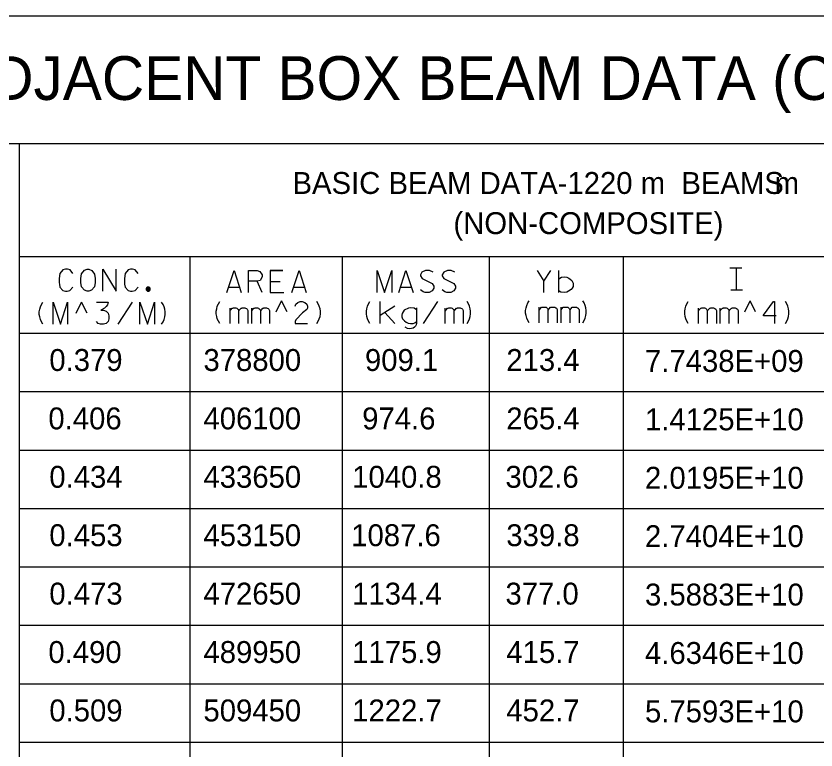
# Model space of a CAD drawing. Extents: x 635698 to 639877, y 296617 to 300175.
# Drawn here: x 635904.4 to 636014, y 299938.2 to 300038.7 of the extents above; entities that cross this region are included whole.
import ezdxf

# ---------------------------------------------------------------- set-up
doc = ezdxf.new("R2010")
doc.units = 0
doc.layers.add('2', color=7, linetype='Continuous')

msp = doc.modelspace()

# ---------------------------------------------------------------- linework, layer by layer
at = {"layer": '2'}
for p, q in [((636461.71, 300038.71), (635698.21, 300038.71)), ((636454.58, 300021.21), (635703.83, 300021.21)), ((635904.83, 300021.21), (635904.83, 299883.21)), ((636087.71, 300005.71), (635904.83, 300005.71)), ((635928.21, 300005.71), (635928.21, 299883.21)), ((635949.08, 300005.71), (635949.08, 299883.21)), ((635969.21, 300005.71), (635969.21, 299883.21)), ((635987.58, 300005.71), (635987.58, 299883.21)), ((636002.21, 300004.21), (636003.83, 300004.21)), ((636002.33, 300001.21), (636003.96, 300001.21)), ((635912.63, 299998.02), (635913.38, 299999.52)), ((635914.13, 299998.02), (635913.38, 299999.52)), ((635940.04, 299998.2), (635940.79, 299999.7)), ((635941.54, 299998.2), (635940.79, 299999.7)), ((636004.24, 299998.2), (636004.99, 299999.7)), ((636005.74, 299998.2), (636004.99, 299999.7)), ((636087.71, 299995.21), (635904.83, 299995.21)), ((636087.71, 299987.21), (635904.83, 299987.21)), ((636087.71, 299979.21), (635904.83, 299979.21)), ((636087.71, 299971.21), (635904.83, 299971.21)), ((636087.71, 299963.21), (635904.83, 299963.21)), ((636087.71, 299955.21), (635904.83, 299955.21)), ((636087.71, 299947.21), (635904.83, 299947.21)), ((636087.71, 299939.21), (635904.83, 299939.21))]:
    msp.add_line(p, q, dxfattribs=at)
for points in [[(635912.19, 300003.43), (635911.81, 300003.93), (635911.43, 300004.02), (635911.17, 300004.02), (635910.82, 300003.93), (635910.42, 300003.43), (635910.32, 300002.77), (635910.32, 300002.41), (635910.32, 300002.18), (635910.35, 300001.97), (635910.42, 300001.59), (635910.82, 300001.12), (635911.17, 300001.02), (635911.39, 300001.02), (635911.79, 300001.12), (635912.19, 300001.59)], [(635914.15, 300004.02), (635914.39, 300004.02), (635914.79, 300003.86), (635915.17, 300003.36), (635915.26, 300002.77), (635915.26, 300002.23), (635915.17, 300001.63), (635914.76, 300001.14), (635914.39, 300001.02), (635914.15, 300001.02), (635913.8, 300001.14), (635913.39, 300001.63), (635913.3, 300002.23), (635913.3, 300002.77), (635913.39, 300003.38), (635913.8, 300003.88), (635914.15, 300004.02)], [(635916.28, 300001.02), (635916.28, 300004.02), (635918.14, 300001.02), (635918.14, 300004.02)], [(635921.12, 300003.43), (635920.74, 300003.93), (635920.36, 300004.02), (635920.1, 300004.02), (635919.75, 300003.93), (635919.35, 300003.43), (635919.25, 300002.77), (635919.25, 300002.41), (635919.25, 300002.18), (635919.28, 300001.97), (635919.35, 300001.59), (635919.75, 300001.12), (635920.1, 300001.02), (635920.32, 300001.02), (635920.72, 300001.12), (635921.12, 300001.59)], [(635933.28, 300000.84), (635934.27, 300003.84), (635935.24, 300000.84)], [(635936.26, 300000.84), (635936.26, 300003.84), (635937.46, 300003.84), (635937.82, 300003.72), (635938.12, 300003.25), (635938.12, 300002.97), (635937.84, 300002.49), (635937.46, 300002.38), (635936.26, 300002.38)], [(635940.96, 300003.84), (635939.24, 300003.84), (635939.24, 300000.84), (635941.08, 300000.84)], [(635939.24, 300003.84), (635940.96, 300003.84)], [(635942.21, 300000.84), (635943.2, 300003.84), (635944.17, 300000.84)], [(635953.86, 300000.84), (635953.86, 300003.84), (635954.9, 300000.84), (635955.87, 300003.84), (635955.87, 300000.84)], [(635956.84, 300000.84), (635957.83, 300003.84), (635958.8, 300000.84)], [(635961.54, 300003.63), (635961.06, 300003.84), (635960.52, 300003.84), (635960.02, 300003.63), (635959.81, 300003.25), (635959.81, 300003.11), (635960.05, 300002.75), (635961.42, 300002.05), (635961.65, 300001.71), (635961.63, 300001.43), (635961.42, 300001.05), (635961.02, 300000.84), (635960.45, 300000.84), (635960.19, 300000.94), (635959.81, 300001.2)], [(635964.51, 300003.63), (635964.04, 300003.84), (635963.5, 300003.84), (635963, 300003.63), (635962.79, 300003.25), (635962.79, 300003.11), (635963.02, 300002.75), (635964.39, 300002.05), (635964.63, 300001.71), (635964.61, 300001.43), (635964.39, 300001.05), (635963.99, 300000.84), (635963.43, 300000.84), (635963.17, 300000.94), (635962.79, 300001.2)], [(635975.79, 300003.84), (635976.73, 300002.4), (635977.68, 300003.84)], [(635978.76, 300000.84), (635978.76, 300003.84)], [(636002.74, 300004.21), (636003.45, 300004.21)], [(636003.1, 300001.21), (636003.1, 300004.21)], [(635978.76, 300002.73), (635979.14, 300002.94), (635979.52, 300002.99), (635979.85, 300002.94), (635980.16, 300002.8), (635980.35, 300002.68), (635980.54, 300002.47), (635980.63, 300002.28), (635980.72, 300002.12), (635980.72, 300001.67), (635980.58, 300001.41), (635980.46, 300001.27), (635980.11, 300001.01), (635979.87, 300000.89), (635979.52, 300000.84), (635979.05, 300000.89), (635978.76, 300001.08)], [(635922.8, 300001.31), (635922.8, 300001.34), (635922.79, 300001.36), (635922.78, 300001.39), (635922.77, 300001.42), (635922.76, 300001.45), (635922.74, 300001.47), (635922.73, 300001.5), (635922.7, 300001.52), (635922.68, 300001.54), (635922.66, 300001.55), (635922.63, 300001.57), (635922.6, 300001.58), (635922.57, 300001.58), (635922.54, 300001.59), (635922.51, 300001.59), (635922.48, 300001.59), (635922.45, 300001.58), (635922.43, 300001.58), (635922.4, 300001.57), (635922.37, 300001.55), (635922.35, 300001.54), (635922.32, 300001.52), (635922.3, 300001.5), (635922.28, 300001.47), (635922.27, 300001.45), (635922.25, 300001.42), (635922.24, 300001.39), (635922.24, 300001.36), (635922.23, 300001.34), (635922.23, 300001.31), (635922.23, 300001.28), (635922.24, 300001.25), (635922.24, 300001.22), (635922.25, 300001.19), (635922.27, 300001.16), (635922.28, 300001.14), (635922.3, 300001.11), (635922.32, 300001.09), (635922.35, 300001.07), (635922.37, 300001.06), (635922.4, 300001.05), (635922.43, 300001.03), (635922.45, 300001.03), (635922.48, 300001.02), (635922.51, 300001.02), (635922.54, 300001.02), (635922.57, 300001.03), (635922.6, 300001.03), (635922.63, 300001.05), (635922.66, 300001.06), (635922.68, 300001.07), (635922.7, 300001.09), (635922.73, 300001.11), (635922.74, 300001.14), (635922.76, 300001.16), (635922.77, 300001.19), (635922.78, 300001.22), (635922.79, 300001.25), (635922.8, 300001.28), (635922.8, 300001.31)], [(635922.74, 300001.31), (635922.74, 300001.33), (635922.73, 300001.35), (635922.73, 300001.38), (635922.72, 300001.4), (635922.71, 300001.42), (635922.7, 300001.44), (635922.68, 300001.46), (635922.66, 300001.47), (635922.65, 300001.49), (635922.63, 300001.5), (635922.61, 300001.51), (635922.58, 300001.52), (635922.56, 300001.53), (635922.54, 300001.53), (635922.51, 300001.53), (635922.49, 300001.53), (635922.47, 300001.53), (635922.44, 300001.52), (635922.42, 300001.51), (635922.4, 300001.5), (635922.38, 300001.49), (635922.36, 300001.47), (635922.35, 300001.46), (635922.33, 300001.44), (635922.32, 300001.42), (635922.31, 300001.4), (635922.3, 300001.38), (635922.29, 300001.35), (635922.29, 300001.33), (635922.29, 300001.31), (635922.29, 300001.28), (635922.29, 300001.26), (635922.3, 300001.24), (635922.31, 300001.21), (635922.32, 300001.19), (635922.33, 300001.17), (635922.35, 300001.16), (635922.36, 300001.14), (635922.38, 300001.12), (635922.4, 300001.11), (635922.42, 300001.1), (635922.44, 300001.09), (635922.47, 300001.09), (635922.49, 300001.08), (635922.51, 300001.08), (635922.54, 300001.08), (635922.56, 300001.09), (635922.58, 300001.09), (635922.61, 300001.1), (635922.63, 300001.11), (635922.65, 300001.12), (635922.66, 300001.14), (635922.68, 300001.16), (635922.7, 300001.17), (635922.71, 300001.19), (635922.72, 300001.21), (635922.73, 300001.24), (635922.73, 300001.26), (635922.74, 300001.28), (635922.74, 300001.31)], [(635922.68, 300001.31), (635922.68, 300001.32), (635922.67, 300001.34), (635922.67, 300001.36), (635922.66, 300001.37), (635922.66, 300001.39), (635922.65, 300001.4), (635922.64, 300001.42), (635922.62, 300001.43), (635922.61, 300001.44), (635922.6, 300001.45), (635922.58, 300001.46), (635922.56, 300001.46), (635922.55, 300001.47), (635922.53, 300001.47), (635922.51, 300001.47), (635922.5, 300001.47), (635922.48, 300001.47), (635922.46, 300001.46), (635922.45, 300001.46), (635922.43, 300001.45), (635922.42, 300001.44), (635922.4, 300001.43), (635922.39, 300001.42), (635922.38, 300001.4), (635922.37, 300001.39), (635922.36, 300001.37), (635922.36, 300001.36), (635922.35, 300001.34), (635922.35, 300001.32), (635922.35, 300001.31), (635922.35, 300001.29), (635922.35, 300001.27), (635922.36, 300001.25), (635922.36, 300001.24), (635922.37, 300001.22), (635922.38, 300001.21), (635922.39, 300001.19), (635922.4, 300001.18), (635922.42, 300001.17), (635922.43, 300001.16), (635922.45, 300001.15), (635922.46, 300001.15), (635922.48, 300001.14), (635922.5, 300001.14), (635922.51, 300001.14), (635922.53, 300001.14), (635922.55, 300001.14), (635922.56, 300001.15), (635922.58, 300001.15), (635922.6, 300001.16), (635922.61, 300001.17), (635922.62, 300001.18), (635922.64, 300001.19), (635922.65, 300001.21), (635922.66, 300001.22), (635922.66, 300001.24), (635922.67, 300001.25), (635922.67, 300001.27), (635922.68, 300001.29), (635922.68, 300001.31)], [(635933.52, 300001.55), (635935.01, 300001.55)], [(635938.12, 300000.84), (635937.44, 300002.38)], [(635939.24, 300002.35), (635940.59, 300002.35)], [(635939.24, 300002.35), (635940.59, 300002.35)], [(635942.45, 300001.55), (635943.94, 300001.55)], [(635957.07, 300001.55), (635958.56, 300001.55)], [(635976.73, 300000.84), (635976.73, 300002.4)], [(635922.62, 300001.31), (635922.62, 300001.32), (635922.62, 300001.33), (635922.61, 300001.34), (635922.61, 300001.35), (635922.6, 300001.36), (635922.6, 300001.37), (635922.59, 300001.38), (635922.58, 300001.38), (635922.58, 300001.39), (635922.57, 300001.4), (635922.56, 300001.4), (635922.55, 300001.41), (635922.54, 300001.41), (635922.52, 300001.41), (635922.51, 300001.41), (635922.5, 300001.41), (635922.49, 300001.41), (635922.48, 300001.41), (635922.47, 300001.4), (635922.46, 300001.4), (635922.45, 300001.39), (635922.44, 300001.38), (635922.44, 300001.38), (635922.43, 300001.37), (635922.42, 300001.36), (635922.42, 300001.35), (635922.41, 300001.34), (635922.41, 300001.33), (635922.41, 300001.32), (635922.41, 300001.31), (635922.41, 300001.29), (635922.41, 300001.28), (635922.41, 300001.27), (635922.42, 300001.26), (635922.42, 300001.25), (635922.43, 300001.24), (635922.44, 300001.24), (635922.44, 300001.23), (635922.45, 300001.22), (635922.46, 300001.21), (635922.47, 300001.21), (635922.48, 300001.21), (635922.49, 300001.2), (635922.5, 300001.2), (635922.51, 300001.2), (635922.52, 300001.2), (635922.54, 300001.2), (635922.55, 300001.21), (635922.56, 300001.21), (635922.57, 300001.21), (635922.58, 300001.22), (635922.58, 300001.23), (635922.59, 300001.24), (635922.6, 300001.24), (635922.6, 300001.25), (635922.61, 300001.26), (635922.61, 300001.27), (635922.62, 300001.28), (635922.62, 300001.29), (635922.62, 300001.31)], [(635922.56, 300001.31), (635922.56, 300001.31), (635922.56, 300001.31), (635922.56, 300001.32), (635922.55, 300001.32), (635922.55, 300001.33), (635922.55, 300001.33), (635922.55, 300001.34), (635922.54, 300001.34), (635922.54, 300001.34), (635922.54, 300001.34), (635922.53, 300001.35), (635922.53, 300001.35), (635922.52, 300001.35), (635922.52, 300001.35), (635922.51, 300001.35), (635922.51, 300001.35), (635922.5, 300001.35), (635922.5, 300001.35), (635922.5, 300001.35), (635922.49, 300001.34), (635922.49, 300001.34), (635922.48, 300001.34), (635922.48, 300001.34), (635922.48, 300001.33), (635922.47, 300001.33), (635922.47, 300001.32), (635922.47, 300001.32), (635922.47, 300001.31), (635922.47, 300001.31), (635922.47, 300001.31), (635922.47, 300001.3), (635922.47, 300001.3), (635922.47, 300001.29), (635922.47, 300001.29), (635922.47, 300001.28), (635922.48, 300001.28), (635922.48, 300001.28), (635922.48, 300001.27), (635922.49, 300001.27), (635922.49, 300001.27), (635922.5, 300001.26), (635922.5, 300001.26), (635922.5, 300001.26), (635922.51, 300001.26), (635922.51, 300001.26), (635922.52, 300001.26), (635922.52, 300001.26), (635922.53, 300001.26), (635922.53, 300001.26), (635922.54, 300001.27), (635922.54, 300001.27), (635922.54, 300001.27), (635922.55, 300001.28), (635922.55, 300001.28), (635922.55, 300001.28), (635922.55, 300001.29), (635922.56, 300001.29), (635922.56, 300001.3), (635922.56, 300001.3), (635922.56, 300001.31)], [(636002.74, 300001.21), (636003.45, 300001.21)], [(635908.06, 299996.52), (635907.87, 299996.83), (635907.73, 299997.16), (635907.64, 299997.49), (635907.59, 299997.84), (635907.59, 299998.2), (635907.64, 299998.55), (635907.73, 299998.88), (635907.87, 299999.21), (635908.06, 299999.52)], [(635909.47, 299996.52), (635909.47, 299999.52), (635910.51, 299996.52), (635911.47, 299999.52), (635911.47, 299996.52)], [(635915.42, 299999.52), (635917, 299999.52), (635916.91, 299999.17), (635916.74, 299998.91), (635916.51, 299998.67), (635916.03, 299998.43), (635916.39, 299998.43), (635916.77, 299998.27), (635917, 299998.03), (635917.12, 299997.65), (635917.12, 299997.25), (635917, 299996.85), (635916.74, 299996.61), (635916.39, 299996.52), (635915.99, 299996.52), (635915.63, 299996.61), (635915.42, 299996.87)], [(635918.4, 299996.52), (635920.36, 299999.52)], [(635921.37, 299996.52), (635921.37, 299999.52), (635922.41, 299996.52), (635923.38, 299999.52), (635923.38, 299996.52)], [(635924.35, 299996.52), (635924.54, 299996.83), (635924.68, 299997.16), (635924.77, 299997.49), (635924.82, 299997.84), (635924.82, 299998.2), (635924.77, 299998.55), (635924.68, 299998.88), (635924.54, 299999.21), (635924.35, 299999.52)], [(635932.31, 299996.59), (635932.12, 299996.89), (635931.98, 299997.23), (635931.89, 299997.56), (635931.84, 299997.91), (635931.84, 299998.26), (635931.89, 299998.62), (635931.98, 299998.95), (635932.12, 299999.28), (635932.31, 299999.59)], [(635942.65, 299998.97), (635942.74, 299999.26), (635943, 299999.49), (635943.35, 299999.59), (635943.61, 299999.59), (635943.97, 299999.49), (635944.23, 299999.23), (635944.35, 299998.97), (635944.35, 299998.71), (635944.25, 299998.5), (635943.66, 299998.05), (635942.74, 299997.11), (635942.65, 299996.87), (635942.65, 299996.59), (635944.35, 299996.59)], [(635945.62, 299996.59), (635945.81, 299996.89), (635945.95, 299997.23), (635946.05, 299997.56), (635946.1, 299997.91), (635946.1, 299998.26), (635946.05, 299998.62), (635945.95, 299998.95), (635945.81, 299999.28), (635945.62, 299999.59)], [(635952.89, 299996.59), (635952.7, 299996.89), (635952.56, 299997.23), (635952.46, 299997.56), (635952.42, 299997.91), (635952.42, 299998.26), (635952.46, 299998.62), (635952.56, 299998.95), (635952.7, 299999.28), (635952.89, 299999.59)], [(635954.29, 299996.59), (635954.29, 299999.59)], [(635960.25, 299996.59), (635962.21, 299999.59)], [(635966.2, 299996.59), (635966.39, 299996.89), (635966.53, 299997.23), (635966.62, 299997.56), (635966.67, 299997.91), (635966.67, 299998.26), (635966.62, 299998.62), (635966.53, 299998.95), (635966.39, 299999.28), (635966.2, 299999.59)], [(635974.7, 299996.7), (635974.51, 299997.01), (635974.37, 299997.34), (635974.28, 299997.67), (635974.23, 299998.03), (635974.23, 299998.38), (635974.28, 299998.74), (635974.37, 299999.07), (635974.51, 299999.4), (635974.7, 299999.7)], [(635982.06, 299996.7), (635982.25, 299997.01), (635982.39, 299997.34), (635982.48, 299997.67), (635982.53, 299998.03), (635982.53, 299998.38), (635982.48, 299998.74), (635982.39, 299999.07), (635982.25, 299999.4), (635982.06, 299999.7)], [(635996.51, 299996.59), (635996.32, 299996.89), (635996.18, 299997.23), (635996.09, 299997.56), (635996.04, 299997.91), (635996.04, 299998.26), (635996.09, 299998.62), (635996.18, 299998.95), (635996.32, 299999.28), (635996.51, 299999.59)], [(636008.54, 299997.63), (636006.84, 299997.63), (636006.84, 299997.74), (636008.17, 299999.59), (636008.33, 299999.59), (636008.33, 299996.59)], [(636009.82, 299996.59), (636010.01, 299996.89), (636010.15, 299997.23), (636010.25, 299997.56), (636010.29, 299997.91), (636010.29, 299998.26), (636010.25, 299998.62), (636010.15, 299998.95), (636010.01, 299999.28), (636009.82, 299999.59)], [(635933.72, 299998.34), (635933.76, 299998.38), (635933.81, 299998.48), (635934.02, 299998.69), (635934.09, 299998.71), (635934.19, 299998.74), (635934.52, 299998.74), (635934.66, 299998.69), (635934.76, 299998.62), (635934.85, 299998.52), (635934.92, 299998.36), (635934.94, 299998.31), (635934.99, 299998.38), (635935.04, 299998.48), (635935.25, 299998.69), (635935.32, 299998.71), (635935.39, 299998.74), (635935.75, 299998.74), (635935.84, 299998.69), (635935.96, 299998.64), (635936.08, 299998.55), (635936.13, 299998.48), (635936.17, 299998.38), (635936.17, 299996.59)], [(635933.72, 299996.59), (635933.72, 299998.71)], [(635934.94, 299996.59), (635934.94, 299998.34)], [(635936.69, 299998.34), (635936.74, 299998.38), (635936.79, 299998.48), (635937, 299998.69), (635937.07, 299998.71), (635937.17, 299998.74), (635937.5, 299998.74), (635937.64, 299998.69), (635937.73, 299998.62), (635937.83, 299998.52), (635937.9, 299998.36), (635937.92, 299998.31), (635937.97, 299998.38), (635938.02, 299998.48), (635938.23, 299998.69), (635938.3, 299998.71), (635938.37, 299998.74), (635938.72, 299998.74), (635938.82, 299998.69), (635938.94, 299998.64), (635939.05, 299998.55), (635939.1, 299998.48), (635939.15, 299998.38), (635939.15, 299996.59)], [(635936.69, 299996.59), (635936.69, 299998.71)], [(635937.92, 299996.59), (635937.92, 299998.34)], [(635956.32, 299998.97), (635954.29, 299997.67)], [(635959.25, 299998.48), (635958.95, 299998.69), (635958.5, 299998.74), (635958.17, 299998.71), (635957.6, 299998.41), (635957.32, 299997.98), (635957.27, 299997.74), (635957.27, 299997.51), (635957.36, 299997.23), (635957.62, 299996.94), (635957.84, 299996.78), (635958.14, 299996.63), (635958.43, 299996.59), (635958.8, 299996.61), (635959.04, 299996.68), (635959.25, 299996.85)], [(635959.25, 299998.74), (635959.25, 299996.59), (635959.21, 299996.4), (635959.14, 299996.23), (635958.99, 299996.07), (635958.8, 299995.97), (635958.59, 299995.9), (635958.33, 299995.85), (635958.03, 299995.9), (635957.72, 299996.07)], [(635963.22, 299998.34), (635963.27, 299998.38), (635963.32, 299998.48), (635963.53, 299998.69), (635963.6, 299998.71), (635963.69, 299998.74), (635964.03, 299998.74), (635964.17, 299998.69), (635964.26, 299998.62), (635964.36, 299998.52), (635964.43, 299998.36), (635964.45, 299998.31), (635964.5, 299998.38), (635964.55, 299998.48), (635964.76, 299998.69), (635964.83, 299998.71), (635964.9, 299998.74), (635965.25, 299998.74), (635965.35, 299998.69), (635965.47, 299998.64), (635965.58, 299998.55), (635965.63, 299998.48), (635965.68, 299998.38), (635965.68, 299996.59)], [(635963.22, 299996.59), (635963.22, 299998.71)], [(635964.45, 299996.59), (635964.45, 299998.34)], [(635976.1, 299998.45), (635976.15, 299998.5), (635976.2, 299998.59), (635976.41, 299998.81), (635976.48, 299998.83), (635976.58, 299998.85), (635976.91, 299998.85), (635977.05, 299998.81), (635977.14, 299998.74), (635977.24, 299998.64), (635977.31, 299998.48), (635977.33, 299998.43), (635977.38, 299998.5), (635977.43, 299998.59), (635977.64, 299998.81), (635977.71, 299998.83), (635977.78, 299998.85), (635978.14, 299998.85), (635978.23, 299998.81), (635978.35, 299998.76), (635978.47, 299998.67), (635978.51, 299998.59), (635978.56, 299998.5), (635978.56, 299996.7)], [(635976.1, 299996.7), (635976.1, 299998.83)], [(635977.33, 299996.7), (635977.33, 299998.45)], [(635979.08, 299998.45), (635979.13, 299998.5), (635979.17, 299998.59), (635979.39, 299998.81), (635979.46, 299998.83), (635979.55, 299998.85), (635979.88, 299998.85), (635980.03, 299998.81), (635980.12, 299998.74), (635980.21, 299998.64), (635980.29, 299998.48), (635980.31, 299998.45), (635980.36, 299998.5), (635980.4, 299998.59), (635980.62, 299998.81), (635980.69, 299998.83), (635980.76, 299998.85), (635981.11, 299998.85), (635981.21, 299998.81), (635981.32, 299998.76), (635981.44, 299998.67), (635981.49, 299998.59), (635981.54, 299998.5), (635981.54, 299996.7)], [(635979.08, 299996.7), (635979.08, 299998.83)], [(635980.31, 299996.7), (635980.31, 299998.45)], [(635997.91, 299998.34), (635997.96, 299998.38), (635998.01, 299998.48), (635998.22, 299998.69), (635998.29, 299998.71), (635998.39, 299998.74), (635998.72, 299998.74), (635998.86, 299998.69), (635998.95, 299998.62), (635999.05, 299998.52), (635999.12, 299998.36), (635999.14, 299998.31), (635999.19, 299998.38), (635999.24, 299998.48), (635999.45, 299998.69), (635999.52, 299998.71), (635999.59, 299998.74), (635999.95, 299998.74), (636000.04, 299998.69), (636000.16, 299998.64), (636000.28, 299998.55), (636000.32, 299998.48), (636000.37, 299998.38), (636000.37, 299996.59)], [(635997.91, 299996.59), (635997.91, 299998.71)], [(635999.14, 299996.59), (635999.14, 299998.34)], [(636000.89, 299998.34), (636000.94, 299998.38), (636000.99, 299998.48), (636001.2, 299998.69), (636001.27, 299998.71), (636001.36, 299998.74), (636001.69, 299998.74), (636001.84, 299998.69), (636001.93, 299998.62), (636002.03, 299998.52), (636002.1, 299998.36), (636002.12, 299998.31), (636002.17, 299998.38), (636002.21, 299998.48), (636002.43, 299998.69), (636002.5, 299998.71), (636002.57, 299998.74), (636002.92, 299998.74), (636003.02, 299998.69), (636003.14, 299998.64), (636003.25, 299998.55), (636003.3, 299998.48), (636003.35, 299998.38), (636003.35, 299996.59)], [(636000.89, 299996.59), (636000.89, 299998.71)], [(636002.12, 299996.59), (636002.12, 299998.34)], [(635954.93, 299998.08), (635956.32, 299996.59)]]:
    msp.add_lwpolyline(points, dxfattribs=at)

# ---------------------------------------------------------------- texts
for s, height, p in [('ADJACENT BOX BEAM DATA (COMPOSITE & NON-COMPOSITE CONSTRUCTION)', 6, (635895.65, 300027.21)), ('BASIC BEAM DATA-1220 m  BEAMS', 3, (635942.28, 300014.34)), ('m', 3, (636008.35, 300014.34)), ('(NON-COMPOSITE)', 3, (635964.33, 300008.84)), ('0.379', 3, (635908.96, 299990.09)), ('378800', 3, (635930.08, 299990.09)), ('909.1', 3, (635952.21, 299990.09)), ('213.4', 3, (635971.58, 299990.09)), ('7.7438E+09', 3, (635990.58, 299989.96)), ('0.406', 3, (635908.83, 299982.09)), ('406100', 3, (635930.08, 299982.09)), ('974.6', 3, (635951.83, 299982.09)), ('265.4', 3, (635971.58, 299982.09)), ('1.4125E+10', 3, (635990.58, 299981.96)), ('0.434', 3, (635908.96, 299974.09)), ('433650', 3, (635930.08, 299974.09)), ('1040.8', 3, (635950.46, 299974.09)), ('302.6', 3, (635971.46, 299974.09)), ('2.0195E+10', 3, (635990.58, 299973.96)), ('0.453', 3, (635908.96, 299966.09)), ('453150', 3, (635930.08, 299966.09)), ('1087.6', 3, (635950.33, 299966.09)), ('339.8', 3, (635971.58, 299966.09)), ('2.7404E+10', 3, (635990.58, 299965.96)), ('0.473', 3, (635908.96, 299958.09)), ('472650', 3, (635930.08, 299958.09)), ('1134.4', 3, (635950.46, 299958.09)), ('377.0', 3, (635971.46, 299958.09)), ('3.5883E+10', 3, (635990.58, 299957.96)), ('0.490', 3, (635908.83, 299950.09)), ('489950', 3, (635930.08, 299950.09)), ('1175.9', 3, (635950.46, 299950.09)), ('415.7', 3, (635971.58, 299950.09)), ('4.6346E+10', 3, (635990.58, 299949.96)), ('0.509', 3, (635908.96, 299942.09)), ('509450', 3, (635930.08, 299942.09)), ('1222.7', 3, (635950.46, 299942.09)), ('452.7', 3, (635971.58, 299942.09)), ('5.7593E+10', 3, (635990.58, 299941.96))]:
    msp.add_text(s, height=height, dxfattribs=at).set_placement(p)

doc.saveas('drawing.dxf')
